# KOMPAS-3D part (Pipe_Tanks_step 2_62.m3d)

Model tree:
1. X Axis
2. Y Axis
3. Z Axis  (labels: Pipe Dn 50)
     Òîëùèíà ñòåíêè 1 = 1

Referenced files in C:\Documents and Settings\kashirsky\Мои документы\Camtasia Studio\Pipelines3D\Tanks\: Tanks_step 2.a3d
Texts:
  Pipe Dn 50
  Steel ASTM A295
  Three Point Plane
  Plane at Angle
  Line and Point Plane
  Axis through Two Vertices
  Axis of Feature
  Axis of Conical Surface
  Axis through Edge
  Trim by Surface
  Trim by Sketch
  Feature with No History
  Intersection Axis of Two Planes
  Two Line Plane
  Line and Face Plane
  Bend by line
  Hole in sheet body
  Cut in sheet body
  Point in CM
  Linear Dimension from Line to Point
  Surface Finish Symbol
  Geometric Tolerance Symbol
  Leader #1
  Leader #2
  Leader #3
  Shape Deviations and Datum
  Node point number
  Mark of coordination axis
  Node point designation
  Mark/Reference designation with leader
  Mark/reference designation on line
  Mark/Reference designation without leader
  Plane of section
